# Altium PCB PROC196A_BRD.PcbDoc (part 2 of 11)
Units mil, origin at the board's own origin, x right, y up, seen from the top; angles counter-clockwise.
Board outline 3346.45 x 4921.26 mil, 8 copper layers (Top Layer, GND1, SIG1, PWR1, PWR2, SIG2, GND2, Bottom Layer), stack 54.534 mil thick; 736 components, 498 nets, 3030 pads, 1279 vias.
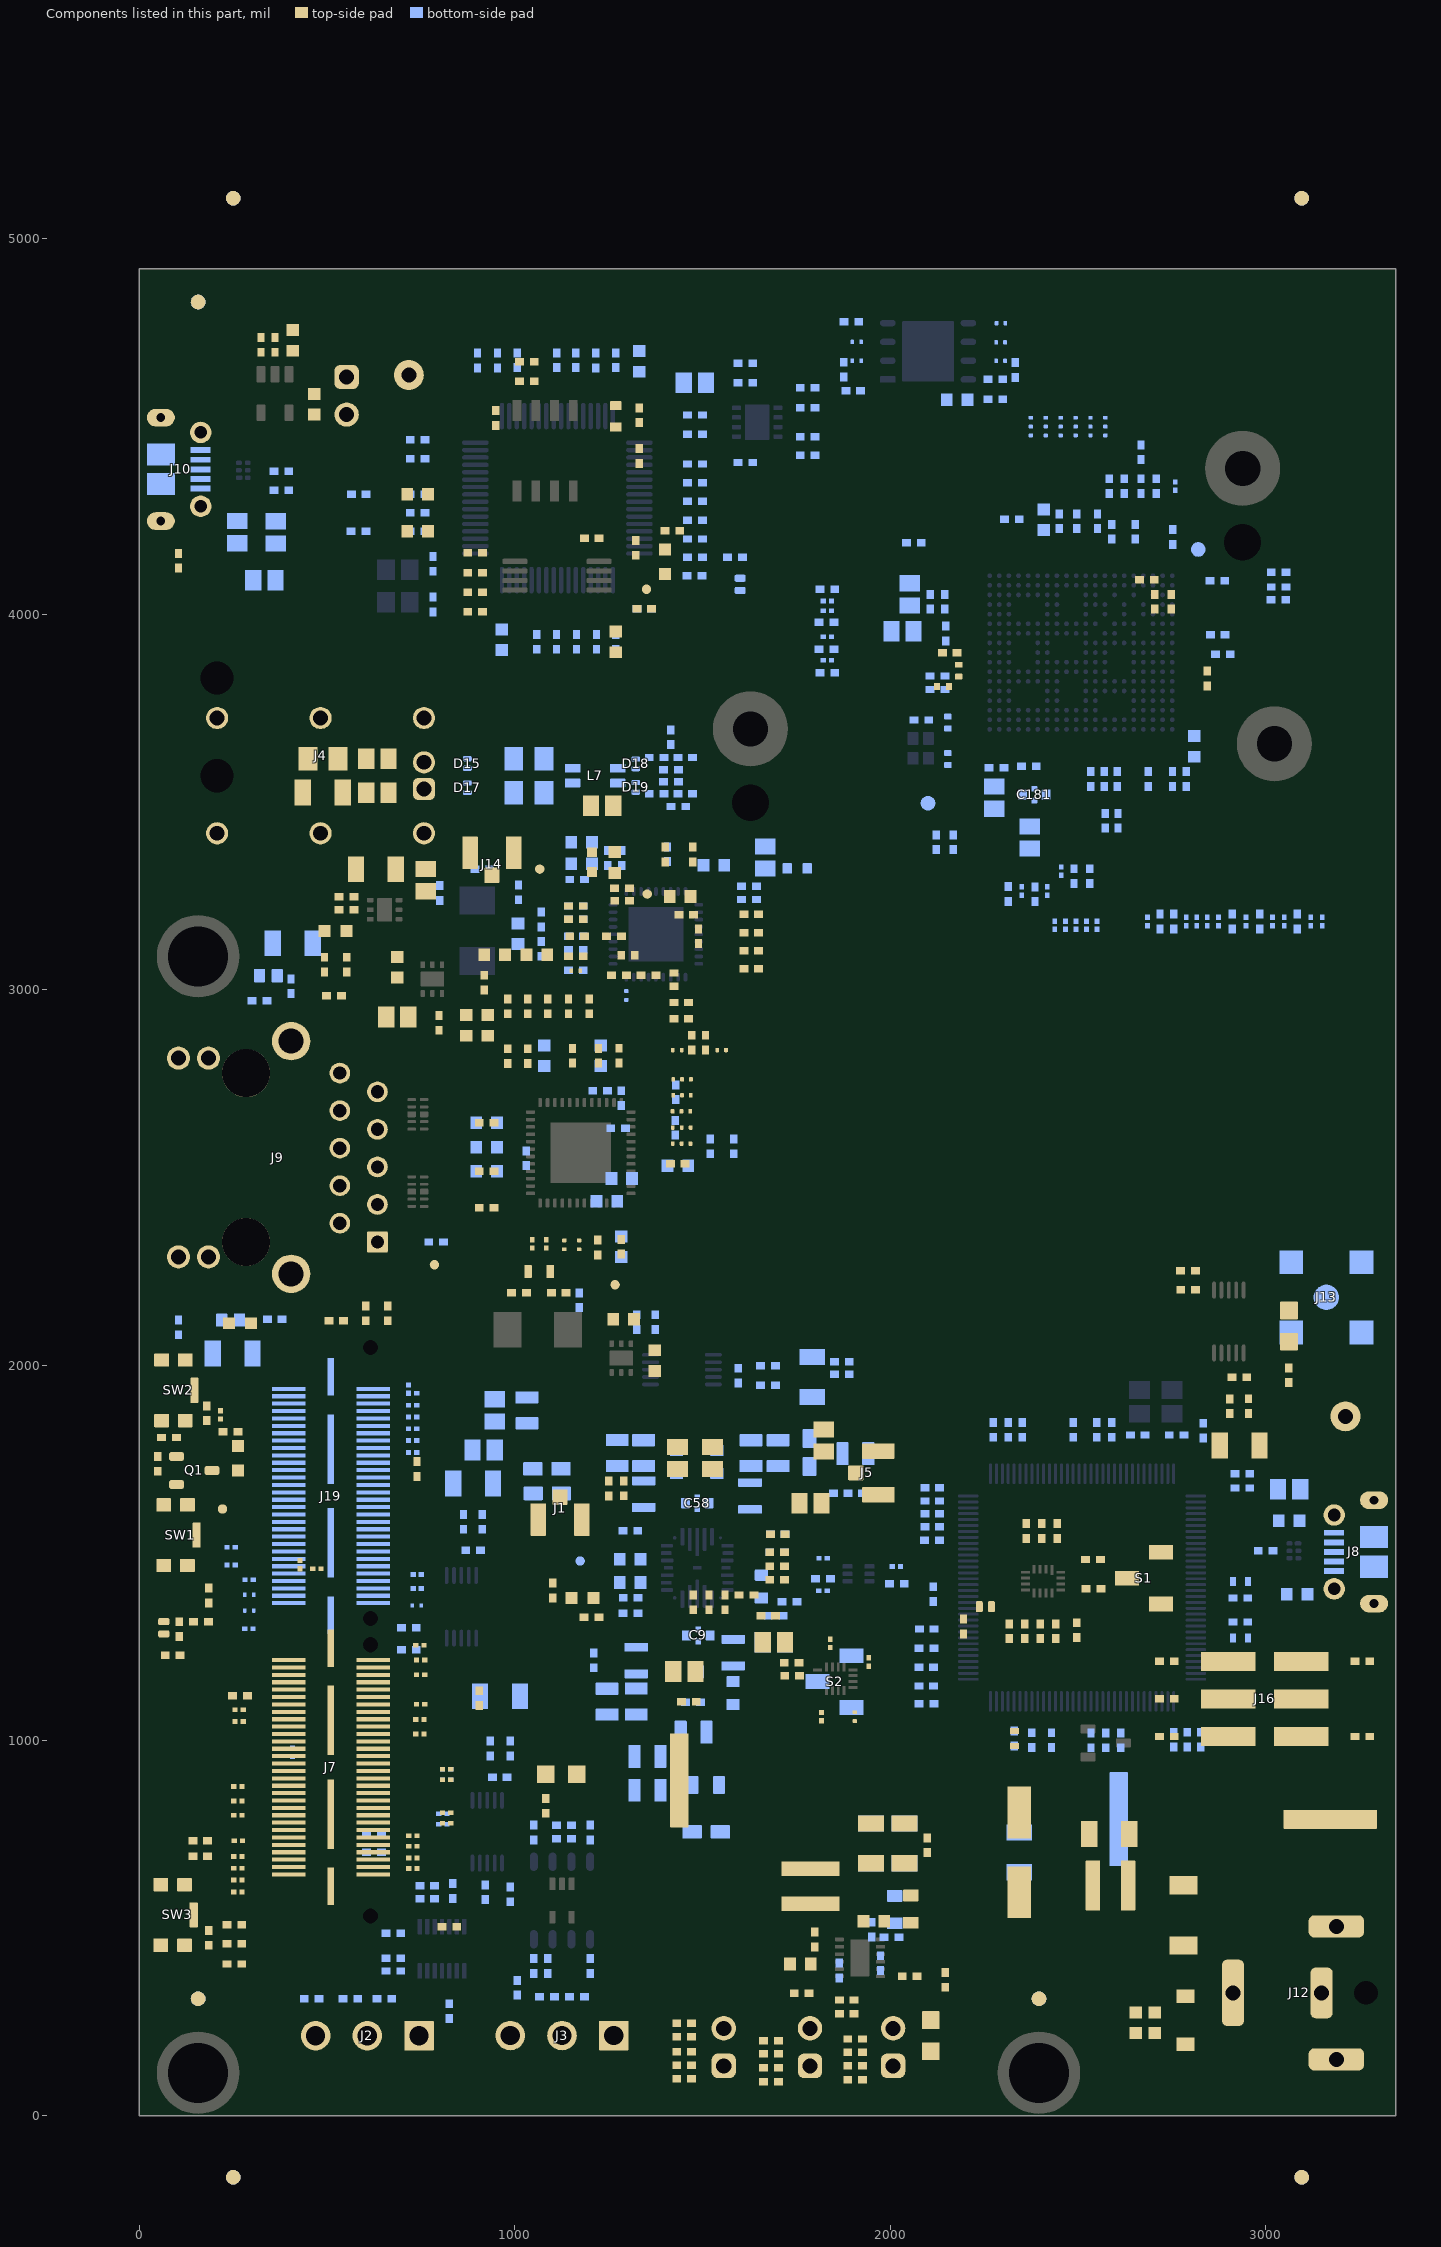
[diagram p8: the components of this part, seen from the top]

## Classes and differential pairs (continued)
differential pair TX2_CLK: +TX2_CLK_P -TX2_CLK_N
differential pair TX1: +TX1_P -TX1_N
differential pair TX0: +TX0_P -TX0_N
differential pair TRD3: +TRD3_P -TRD3_N
differential pair TRD2: +TRD2_P -TRD2_N
differential pair TRD1: +TRD1_P -TRD1_N
differential pair ETH_TRD: +ETH_TRD_P -ETH_TRD_N
differential pair CSI2_CLK: +CSI2_CLK_P -CSI2_CLK_N
differential pair CSI2_1: +CSI2_1_P -CSI2_1_N
differential pair CSI2_0: +CSI2_0_P -CSI2_0_N
differential pair LVDS_TX3_FRCLK: +LVDS_TX3_FRCLK_P -LVDS_TX3_FRCLK_N
differential pair LVDS_TX2_CLK: +LVDS_TX2_CLK_P -LVDS_TX2_CLK_N
differential pair LVDS_TX1: +LVDS_TX1_P -LVDS_TX1_N
differential pair LVDS_TX0: +LVDS_TX0_P -LVDS_TX0_N
differential pair CAN_A: +CANA_P -CANA_N
differential pair CAN_B: +CANB_P -CANB_N
differential pair FTDI_USBD: +FTDI_USBD_P -FTDI_USBD_N
differential pair XDSET_1_D: +XDSET_1_D_P -XDSET_1_D_N
differential pair ETH_TD_4: +TD_4_P -TD_4_N
differential pair ETH_TD_3: +TD_3_P -TD_3_N
differential pair ETH_TD_2: +TD_2_P -TD_2_N
differential pair ETH_TD_1: +TD_1_P -TD_1_N
differential pair CSI2_RX0_CLK: +CSI2_RX0_CLK_P -CSI2_RX0_CLK_N
differential pair CSI2_RX0_1: +CSI2_RX0_1_P -CSI2_RX0_1_N
differential pair CSI2_RX0_0: +CSI2_RX0_0_P -CSI2_RX0_0_N

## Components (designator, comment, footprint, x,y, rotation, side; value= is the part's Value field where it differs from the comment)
C1 "GCM188R71C105KA64D" 0603L 2178.63,4571.73 r0 bottom value=1uF
C2 "CGA2B3X7R1H104K050BB" 0402L 2280.38,4572.73 r180 bottom value=0.1uF
C3 "GCM188R70J225KE22D" 0603L 1307.54,1483.26 r0 bottom value=2.2uF
C4 "C0805C106J8RACAUTO" 0805L 946.64,1879.52 r90 bottom value=10uF
C5 "GCM155R71C224KE02D" 0402L 2107,4033.64 r270 bottom value=0.22uF
C6 "GCJ188C70J475KE02J" FP-GCJ188C70J475KE02J_0603-MFG 1458.73,1183.19 r180 bottom value=4.7µF
C7 "GCM21BR71A106KE22L" 0805L 1526.87,1752.55 r90 top value=10uF
C8 "GCJ188C70J475KE02J" FP-GCJ188C70J475KE02J_0603-MFG 1581.73,1125.98 r90 bottom value=4.7µF
C9 "NFM18HC105C1C3D" FP-NFM18HC105C1C3D_0603-MFG 1489.02,1279.6 r180 bottom
C10 "GCM188R71C105KA64D" 0603L 1761.22,404.47 r180 top value=1uF
C11 "GCM155R71C104KA55D" 0402L 766.94,578.34 r0 bottom value=0.1uF
C12 "GCM155R71C104KA55D" 0402L 834.66,598.77 r270 bottom value=0.1uF
C13 "GCM155R71H472KA37D" 0402L 458.81,311.94 r0 bottom value=4700pF
C14 "GCM155R71A104KA55D" 0402L 960.06,901.73 r0 bottom value=0.1uF
C15 "GCM21BR71A106KE22L" 0805L 1433.57,1752.55 r90 top value=10uF
C16 "GCM155R71C104KA55D" 0402L 1131.24,738.16 r0 bottom value=0.1uF
C17 "GCM155R71A104KA55D" 0402L 1595.68,1972.04 r270 bottom value=0.1uF
C18 "C0402C104K8RACTU" 0402L 1739.01,1172.28 r0 top value=0.1uF
C19 "GCM155R71A104KA55D" 0402L 2930.36,1967.92 r0 top value=0.1uF
C20 "GCM155R71C104KA55D" 0402L 1200.93,398.98 r90 bottom value=0.1uF
C21 "GCM155R71C224KE02D" 0402L 1799.66,469.84 r90 top value=0.22uF
C22 "GCM155R71C224KE02D" 0402L 2099.39,720.8 r90 top value=0.22uF
C23 "GCM31CR71A226KE02L" 1206_180L 2038.6,725.8 r270 bottom value=22uF
C24 "GCM155R71H472KA37D" 0402L 1006.26,341.2 r270 bottom value=4700pF
C25 "GCM31CR71A226KE02L" 1206_180L 2038.6,725.8 r270 top value=22uF
C26 "GCM31CR71A226KE02L" 1206_180L 1949.49,725.8 r270 bottom value=22uF
C27 "C0603C104K4RACAUTO" FP-C0603C104K4RACAUTO_0603-MFG 243.02,2119.9 r0 bottom
C28 "C0603C104K4RACAUTO" FP-C0603C104K4RACAUTO_0603-MFG 343.71,3037.46 r0 bottom
C29 "GCM31CR71A226KE02L" 1206_180L 1949.49,725.8 r270 top value=22uF
C30 "GCM1555C1H270JA16D" 0402L 1117.32,2192.39 r0 top value=27pF
C31 "GCM21BR71A106KE22L" 0805L 1452.03,1183.68 r0 top value=10uF
C32 "GCM188R70J225KE22D" 0603L 1058.91,3092.81 r0 top value=2.2uF
C33 "GCM1555C1H270JA16D" 0402L 1011.33,2192.39 r180 top value=27pF
C34 "GCM155R71H102KA37D" 0402L 798.3,2911.52 r90 top value=1000pF
C35 "CGA2B3X7R1H103K050BB" 0402L 1356.52,3038.39 r0 top value=0.01uF
C36 "GCM155R71C104KA55D" 0402L 1277.78,3038.39 r0 top value=0.1uF
C37 "GCM21BR71A106KE22L" 0805L 1667.73,3352.16 r90 bottom value=10uF
C38 "CGA4J3X7R1H225K125AB" 0805L 687.02,2927.1 r180 top value=2.2uF
C39 "CL21B106KOQNNNE" 0805L 333.24,4091.18 r180 bottom value=10uF
C40 "GCM188R70J225KE22D" 0603L 1530.41,3331.1 r180 bottom value=2.2uF
C41 "GCM155C71A105KE38D" 0402_070 2330.78,1005.16 r270 top value=1uF
C42 "C0402C104K8RACTU" 0402L 2487.6,1827.41 r270 bottom value=0.1uF
C43 "C0402C104K8RACTU" 0402L 2933.19,1379.55 r180 bottom value=0.1uF
C44 "CGA2B3X7R1H103K050BB" 0402L 1624.26,3240.41 r0 bottom value=0.01uF
C45 "CL21B106KOQNNNE" 0805L 3062.92,1669.54 r0 bottom value=10uF
C46 "GCM155R71C104KA55D" 0402L 1624.26,3275.88 r180 bottom value=0.1uF
C47 "C0402C104K8RACTU" 0402L 949.01,4522.91 r90 top value=0.1uF
C48 "GCM188R71C105KA64D" 0603L 687.02,3059.84 r270 top value=1uF
C49 "C0402C104K8RACTU" 0402L 2314.64,1827.41 r90 bottom value=0.1uF
C50 "C0402C103K4RACTU" 0402L 2114.73,1389.65 r90 bottom value=0.01uF
C51 "GCM188R70J225KE22D" 0603L 1178.11,3336.02 r180 bottom value=2.2uF
C52 "CGA2B3X7R1H103K050BB" 0402L 1284.68,3350.79 r90 bottom value=0.01uF
C53 "GCM188R71C105KA64D" 0603L 1229.15,2824.15 r90 bottom value=1uF
C54 "GCM155R71C104KA55D" 0402L 1248.1,3350.79 r270 bottom value=0.1uF
C55 "GRM155R71E473KA88D" 0402L 1162.88,3222.97 r0 bottom value=0.047uF
C56 "GCM188R71C105KA64D" 0603L 925.03,2580.18 r180 bottom value=1uF
C57 "GCM155R71A104KA55D" 0402L 1030.83,2551.09 r270 bottom value=0.1uF
C58 "NFM18HC105C1C3D" FP-NFM18HC105C1C3D_0603-MFG 1486.12,1632.06 r180 bottom
C59 "GCM188R71C105KA64D" 0603L 925.03,2516.33 r180 bottom value=1uF
C60 "GCM188R71C105KA64D" 0603L 1373.01,2012.02 r90 top value=1uF
C61 "GCM155C71A105KE38D" 0402_070 2933.5,1423.7 r0 bottom value=1uF
C62 "GCM155C71A105KE38D" 0402_070 2933.5,1272.74 r0 bottom value=1uF
C63 "GCM1555C1H8R0DA16D" 0402L 2763.45,1813.63 r180 bottom
C64 "C0402C104K8RACTU" 0402L 2933.19,1315.66 r180 bottom value=0.1uF
C65 "GCM188R71C105KA64D" 0603L 1290.01,2122.43 r180 top value=1uF
C66 "C0402C103K4RACTU" 0402L 2614.2,1000.36 r90 bottom value=0.01uF
C67 "C0402C104K8RACTU" 0402L 2574.86,1000.36 r90 bottom value=0.1uF
C68 "C1608X7S1A475K080AC" 0603L 741.44,4221.1 r180 top value=4.7uF
C69 "C0402C104K8RACTU" 0402L 741.44,4221.1 r0 bottom value=0.1uF
C70 "GCM1555C1H8R0DA16D" 0402L 2659.65,1813.63 r180 bottom
C71 "C0402C104K8RACTU" 0402L 2938.61,1710.31 r180 bottom value=0.1uF
C72 "C1608X7S1A475K080AC" 0603L 741.44,4319.53 r180 top value=4.7uF
C73 "C0402C104K8RACTU" 0402L 741.44,4319.53 r0 bottom value=0.1uF
C74 "C1005X7S1A225K050BC" 0402_065L 2550.86,1827.41 r270 bottom value=2.2uF
C75 "C0402C104K8RACTU" 0402L 2590.64,1827.41 r270 bottom value=0.1uF
C76 "C0402C104K8RACTU" 0402L 2330.38,1005.16 r90 bottom value=0.1uF
C77 "C0402C104K8RACTU" 0402L 1345,4014.41 r0 bottom value=0.1uF
C78 "C0402C104K8RACTU" 0402L 1345,4014.41 r0 top value=0.1uF
C79 "C1608X7S1A475K080AC" 0603L 965.97,3932.47 r270 bottom value=4.7uF
C80 "CGA2B3X7R1H104K050BB" 0402L 825.99,278.87 r270 bottom value=0.1uF
C81 "GCM155R71A104KA55D" 0402L 889.05,1506.69 r0 bottom value=0.1uF
C82 "C0402C104K8RACTU" 0402L 1480.11,4400.69 r0 bottom value=0.1uF
C83 "GCM1555C1H8R0DA16D" 0402L 782.36,4134.49 r90 bottom
C84 "GCM1555C1H8R0DA16D" 0402L 782.36,4026.22 r270 bottom
C85 "C1005X7S1A225K050BC" 0402_065L 1614.4,4404.56 r0 bottom value=2.2uF
C86 "C0402C104K8RACTU" 0402L 1205.14,4202.72 r180 top value=0.1uF
C87 "GCM188R71C105KA64D" 0603L 1332.18,4674.03 r90 bottom value=1uF
C88 "C0402C104K8RACTU" 0402L 1269.17,4677.01 r90 bottom value=0.1uF
C89 "C0402C104K8RACTU" 0402L 1480.11,4250.38 r0 bottom value=0.1uF
C90 "GCM188R71C105KA64D" 0603L 1268.76,3926.57 r270 top value=1uF
C91 "C0402C104K8RACTU" 0402L 1268.76,3926.57 r270 bottom value=0.1uF
C92 "GCM155R71C224KE02D" 0402L 2497.58,4248.14 r270 bottom value=0.22uF
C93 "04025A150FAT2A" 0402L 1614.4,4617.01 r0 bottom value=15pF
C94 "C1005X7S1A225K050BC" 0402_065L 1614.4,4668.86 r0 bottom value=2.2uF
C95 "GCM1555C1H270JA16D" 0402L 1070.29,3108.78 r270 bottom value=27pF
C96 "GCM155R71C224KE02D" 0402L 2653.45,4220.14 r270 bottom value=0.22uF
C97 "C0402C104K8RACTU" 0402L 378.25,4330.82 r0 bottom value=0.1uF
C98 "C0402C104K8RACTU" 0402L 2541.82,1403.8 r180 top value=0.1uF
C99 "EEHZC1V680XP" SM_RADIAL_6.3BMM 2344.16,701.75 r90 top value=68uF
C100 "C3216X7R1H475K160AC" 1206_180L 2584.03,750.92 r180 top value=4.7uF
C101 "C3216X7R1H475K160AC" 1206_180L 2344.16,701.75 r90 bottom value=4.7uF
C102 "GRT155R70J105KE01D" FP-GRT155R70J105KE01D_0402-MFG 2182.53,3849.99 r90 top
C103 "GRT155R70J105KE01D" FP-GRT155R70J105KE01D_0402-MFG 2141,3807.81 r180 top
C104 "CGA3E3X8R1H104K080AB" 0603L 2654.4,248.05 r270 top value=0.1uF
C105 "GCM155R71C104KA55D" 0402L 105.96,1296.64 r90 top value=0.1uF
C106 "GCM1555C1H3R9BA16D" FP-GCM1555C1H3R9BA16D_0402-MFG 2153.98,3711.71 r90 bottom value=3.9pF
C107 "GCM155R71C224KE02D" 0402L 2126.32,3835.75 r0 bottom value=0.22uF
C108 "GCM1555C1H3R9BA16D" FP-GCM1555C1H3R9BA16D_0402-MFG 2153.98,3614.48 r270 bottom value=3.9pF
C109 "C0402C103K4RACTU" 0402L 2791.65,1002.31 r90 bottom value=0.01uF
C110 "GCM21BR71A106KE22L" 0805L 2277.53,3511.81 r270 bottom value=10uF
C111 "GCM155R71C224KE02D" 0402L 2126.32,3799.81 r0 bottom value=0.22uF
C112 "GCM21BR71A106KE22L" 0805L 2052,4053.32 r90 bottom value=10uF
C113 "GCM155R71C224KE02D" 0402L 2145.52,4033.64 r270 bottom value=0.22uF
C114 "GCM21BR71A106KE22L" 0805L 2033,3955 r180 bottom value=10uF
C115 "GCM155R71C224KE02D" 0402L 2148.52,3948.96 r90 bottom value=0.22uF
C116 "GCM21BR71A106KE22L" 0805L 2371.99,3405.53 r270 bottom value=10uF
C117 "GCM155R71C224KE02D" 0402L 2369.69,3595.08 r180 bottom value=0.22uF
C118 "CGA4J1X7R1H475K125AC" FP-CGA4J1X7R1H475K125AC_0805-MFG 2055.31,550.68 r270 top value=4.7µF
C119 "GCM21BR71A106KE22L" 0805L 1690.38,1261.41 r0 bottom value=10uF
C120 "GCM21BR71A106KE22L" 0805L 1690.38,1261.41 r0 top value=10uF
C121 "GCM1555C1H270JA16D" 0402L 1070.29,3187.16 r90 bottom value=27pF
C122 "GCM21BR71A106KE22L" 0805L 1232.99,3489.89 r0 top value=10uF
C123 "GCM188R70J225KE22D" 0603L 1307.54,1420.78 r0 bottom value=2.2uF
C124 "GCJ188C70J475KE02J" FP-GCJ188C70J475KE02J_0603-MFG 1657.09,1409.65 r270 bottom value=4.7µF
C125 "CGA4J1X7T0J226M" 0805_155 1629.38,1765.47 r90 bottom value=22uF
C126 "CGA3E3X8R1H104K080AB" 0603L 2705.05,248.05 r270 top value=0.1uF
C127 "CGA4J1X7T0J226M" 0805_155 1701.58,1765.47 r90 bottom value=22uF
C128 "CGA2B3X7R1H104K050BB" 0402L 252.91,509.12 r0 top value=0.1uF
C129 "CGA4J1X7T0J226M" 0805_155 1323.84,1103.87 r270 bottom value=22uF
C130 "CGA4J1X7T0J226M" 0805_155 1245.97,1103.35 r270 bottom value=22uF
C131 "GCM155R71C104KA55D" 0402L 1832.79,4066.99 r0 bottom value=0.1uF
C132 "CGA4J1X7T0J226M" 0805_155 1343.24,1765.47 r90 bottom value=22uF
C133 "C0402C104K8RACTU" 0402L 1821.32,1431.2 r180 bottom value=0.1uF
C134 "CGA4J1X7T0J226M" 0805_155 1273.18,1765.68 r90 bottom value=22uF
C135 "GCM155R71C104KA55D" 0402L 1832.79,3844.85 r0 bottom value=0.1uF
C136 "GCM155R71C104KA55D" 0402L 1830.67,3906.58 r0 bottom value=0.1uF
C137 "GCM188R70J225KE22D" 0603L 2809.92,3648 r90 bottom value=2.2uF
C138 "GCM155R71C224KE02D" 0402L 2749.31,4033.5 r270 top value=0.22uF
C139 "GCM155R71C224KE02D" 0402L 2450.27,4248.14 r270 bottom value=0.22uF
C140 "GCM155R71C224KE02D" 0402L 2535.04,3561.4 r90 bottom value=0.22uF
C141 "GCM155R71C224KE02D" 0402L 2705.12,4033.5 r270 top value=0.22uF
C142 "GCM155R71C224KE02D" 0402L 2684,4092 r180 top value=0.22uF
C143 "CGA4J1X7T0J226M" 0805_155 1476.56,1022 r0 bottom value=22uF
C144 "GCJ188C70J475KE02J" FP-GCJ188C70J475KE02J_0603-MFG 1538.4,1741.87 r270 bottom value=4.7µF
C145 "GCM188R71C105KA64D" 0603L 408.44,4729.82 r90 top value=1uF
C146 "GCM188R70J225KE22D" 0603L 2408.92,4252.13 r270 bottom value=2.2uF
C147 "GCM188R70J225KE22D" 0603L 1266.14,3338.9 r90 top value=2.2uF
C148 "GCM155R71A104KA55D" 0402L 1285.83,3270.67 r0 top value=0.1uF
C149 "GCM188R70J225KE22D" 0603L 466.12,4559.69 r270 top value=2.2uF
C150 "GCM155R71C104KA55D" 0402L 2324.28,4253 r180 bottom value=0.1uF
C151 "CGA4J1X7T0J226M" 0805_155 1032.32,1879.52 r90 bottom value=22uF
C152 "C0805C106J8RACAUTO" 0805L 917.11,1773.67 r180 bottom value=10uF
C153 "GCJ188C70J475KE02J" FP-GCJ188C70J475KE02J_0603-MFG 1430.78,1741.87 r270 bottom value=4.7µF
C154 "CGA2B3X7R1H103K050BB" 0402L 1286.27,3236.75 r0 top value=0.01uF
C155 "GRM1555C1H470FA01D" 0402L 1415.62,3672.6 r270 bottom value=47pF
C156 "GRM1555C1H220FA01D" 0402L 1454.38,3618.51 r0 bottom value=22pF
C157 "CGA4J2X7R2A104K125AA" 0805_HV 1037.67,3615.54 r0 bottom value=0.1uF
C158 "GCM155R71A104KA55D" 0402L 1434.17,2536.83 r0 top value=0.1uF
C159 "GCM188R71C105KA64D" 0603L 1078.54,2824.03 r90 bottom value=1uF
C160 "GCM155R71A104KA55D" 0402L 1153.91,2824.15 r90 top value=0.1uF
C161 "CGA4J2X7R2A104K125AA" 0805_HV 1037.67,3524.99 r0 bottom value=0.1uF
C162 "GRM1555C1H220FA01D" 0402L 1454.38,3522.02 r180 bottom value=22pF
C163 "GCM155R71C224KE02D" 0402L 2570.08,3561.4 r90 bottom value=0.22uF
C164 "GCM155R71C224KE02D" 0402L 2552.55,4248.14 r270 bottom value=0.22uF
C165 "GCM155R71C224KE02D" 0402L 2753.34,4206 r270 bottom value=0.22uF
C166 "GRM1555C1H470FA01D" 0402L 1435.86,3488.17 r0 bottom value=47pF
C167 "GRM31BR73A472KW01L" 1206L 488.5,3525.09 r180 top value=4700pF
C168 "GCM155R71C224KE02D" 0402L 2283.59,3591.08 r0 bottom value=0.22uF
C169 "CGA4J1X7T0J226M" 0805_155 1907.41,1764 r0 bottom value=22uF
C170 "GCM155R71C224KE02D" 0402L 2873,3945.81 r180 bottom value=0.22uF
C171 "GCM188R70J225KE22D" 0603L 1440.53,3248.3 r180 top value=2.2uF
C172 "GCM155R71C224KE02D" 0402L 2844.55,3829 r270 top value=0.22uF
C173 "CGA4J1X7R1H475K125AC" FP-CGA4J1X7R1H475K125AC_0805-MFG 2012.3,549.25 r270 bottom value=4.7µF
C174 "GCM155R71C224KE02D" 0402L 2590.78,4220.14 r270 bottom value=0.22uF
C175 "GCM155R71C224KE02D" 0402L 2605.12,3561.4 r90 bottom value=0.22uF
C176 "GCM155R71C224KE02D" 0402L 2886.48,3893.25 r180 bottom value=0.22uF
C177 "GCM155R71C224KE02D" 0402L 2871.85,4089 r180 bottom value=0.22uF
C178 "GCM155R71A104KA55D" 0402L 1456.97,3199.21 r180 top value=0.1uF
C180 "CGA2B3X7R1H473K050BB" 0402L 2158.91,3897.25 r180 top value=0.047uF
C181 "NFM18HC105C1C3D" FP-NFM18HC105C1C3D_0603-MFG 2384.16,3519.56 r180 bottom
C182 "CGA2B3X7R1H103K050BB" 0402L 1489.66,3142.55 r270 top value=0.01uF
C183 "GCM188R71C105KA64D" 0603L 1245.36,2436.07 r0 bottom value=1uF
C184 "GCM155R71A104KA55D" 0402L 1220.92,2313.15 r270 top value=0.1uF
C185 "GCM155R71A104KA55D" 0402L 1223.15,2824.15 r90 top value=0.1uF
C186 "GCM188R71C105KA64D" 0603L 1434.58,2531.54 r0 bottom value=1uF
C187 "GCM188R71C105KA64D" 0603L 925.03,2645.15 r180 bottom value=1uF
C188 "GCM155R71A104KA55D" 0402L 925.03,2516.33 r180 top value=0.1uF
C189 "GCM155R71A104KA55D" 0402L 925.03,2645.15 r180 top value=0.1uF
C190 "GCM188R71C105KA64D" 0603L 1284.2,2315.32 r270 bottom value=1uF
C191 "GCM155R71A104KA55D" 0402L 1284.2,2315.32 r270 top value=0.1uF
C192 "GCM188R71C105KA64D" 0603L 1285.02,2497.07 r180 bottom value=1uF
C193 "GCM155R71A104KA55D" 0402L 1275.32,2630.46 r180 bottom value=0.1uF
C194 "C0805C106J8RACAUTO" 0805L 1823.26,1799.07 r90 top value=10uF
C195 "CGA3E3X7R1H224K080AB" 0603L 1956.84,517.83 r180 top value=0.22uF
C196 "GCM21BR71A106KE22L" 0805L 763.1,3291.92 r90 top value=10uF
C197 "CGA5L1X7R1H106K160AE" 1206L 629.98,3320.94 r0 top value=10uF
C198 "C0805C106J8RACAUTO" 0805L 1787.88,1631.56 r180 top value=10uF
C199 "GCM155R71C224KE02D" 0402L 1464.06,1103 r0 top value=0.22uF
C200 "GCM155R71C104KA55D" 0402L 1474.75,1101.8 r0 bottom value=0.1uF
C201 "CGA4J1X7T0J226M" 0805_155 1353.58,867.28 r180 bottom value=22uF
C202 "CGA4J1X7T0J226M" 0805_155 1353.58,957.28 r180 bottom value=22uF
"CAUTION HOT SURFACE1" "CAUTION HOT SURFACE" IEC_HotSurface_Small 1476.53,1588.15 r0 top locked
D1 "TLMY1000-GS08" TLMx1000_Yellow 1269.17,4527.56 r270 top value=Yellow
D2 "SMS3923-040LF" SOD-882 2253.83,1356.5 r0 top value=V
D3 "ATV02W280B-HF" SOD-123 2787.46,254.64 r90 top value=28V
D4 "SMS3923-040LF" SOD-882 64.98,1300.09 r90 top value=V
D5 "SMS3923-040LF" SOD-882 1600.48,4079.94 r270 bottom value=V
D6 "SML-LXT0805GW-TR" SML_Green_0805 3062.49,2103.82 r90 top value=Green
D7 "LS L29K-G1J2-1-Z" "LS L29K_Red" 522.64,3156.33 r180 top value=Red
D8 "LS L29K-G1J2-1-Z" "LS L29K_Red" 268.01,2111.42 r180 top value=Red
D9 "SML-E12Y8WT86" SML-E1_Yellow 1400.32,4140.29 r90 top value=Yellow
D10 "SML-P12YTT86" LED_SMLP12_YELLOW 1424,3026.81 r90 top value=Yellow
D11 "FSV530AF" SMAF 2781.96,534.03 r270 top value=30V
D12 "SML-LXT0805GW-TR" SML_Green_0805 2108.41,213.6 r270 top value=Green
D13 "SML-E12Y8WT86" SML-E1_Yellow 262.47,1751.71 r90 top value=Yellow
D14 "SML-P12DTT86" LED_SMLP12_ORANGE 1301.91,3091.95 r0 top value=Orange
D15 "TPD1E05U06QDPYRQ1" DPY0002A 873.77,3602.58 r90 bottom
D16 "SML-LXT0805GW-TR" SML_Green_0805 1124.1,910.02 r0 top value=Green
D17 "TPD1E05U06QDPYRQ1" DPY0002A 873.77,3537.94 r270 bottom
D18 "TPD1E05U06QDPYRQ1" DPY0002A 1322.29,3601.54 r90 bottom
D19 "TPD1E05U06QDPYRQ1" DPY0002A 1322.29,3538.98 r270 bottom
Designator9 "Comment" VGROVE_1-6_45A 9544.57,4519.72 r0 top
DS2 "LS L29K-G1J2-1-Z" "LS L29K_Red" 1180.58,1379.84 r0 top value=Red
"ESD Susceptible1" "ESD Susceptible" ESD_Overlay_Small 1175.93,1141.93 r0 top
FB1 "BLM18HE102SN1D" FP-BLM18AG102SH1D_0603-MFG 1752.76,3323.23 r180 bottom value="1000 ohm"
FB2 "BLM18KG601SH1" "FP-BLM18KG601SH1_0603 (1608 Metric)-MFG" 1206.02,3340.14 r270 top
FID1 "Fiducial" Fiducial10-20 2101,3496.81 r90 bottom
FID2 "Fiducial" Fiducial10-20 2820.77,4173 r90 bottom
FID3 "Fiducial" Fiducial10-20 156.55,311.77 r90 top
FID4 "Fiducial" Fiducial10-20 156.55,311.77 r90 bottom
FID5 "Fiducial" Fiducial10-20 2396.55,311.77 r90 bottom
FID6 "Fiducial" Fiducial10-20 2396.55,311.77 r90 top
FID7 "Fiducial" Fiducial10-20 250,5108.66 r90 bottom
FID8 "Fiducial" Fiducial10-20 250,5108.66 r90 top
FID9 "Fiducial" Fiducial10-20 156.55,4831.99 r90 bottom
FID10 "Fiducial" Fiducial10-20 156.55,4831.99 r90 top
FID11 "Fiducial" Fiducial10-20 3096.45,5108.66 r90 bottom
FID12 "Fiducial" Fiducial10-20 250,-163.78 r90 top
FID13 "Fiducial" Fiducial10-20 250,-163.78 r90 bottom
FID14 "Fiducial" Fiducial10-20 3096.45,5108.66 r90 top
FID15 "Fiducial" Fiducial10-20 3096.45,-163.78 r90 bottom
FID16 "Fiducial" Fiducial10-20 3096.45,-163.78 r90 top
J1 "1909763-1" "FP-1909763-1_SMT_JACK _CONN-MFG" 1120.81,1585.4 r180 top
J2 "OSTTF030161" FP-OSTTF030161_PTH_TERMINAL_BLOCK-MFG 607.34,195.71 r180 top locked
J3 "OSTTF030161" FP-OSTTF030161_PTH_TERMINAL_BLOCK-MFG 1125.93,196.1 r180 top locked
J4 "9-2304372-9" TE_9-2304372-9 207.07,3570.26 r90 bottom
J5 "1909763-1" "FP-1909763-1_SMT_JACK _CONN-MFG" 1971.89,1712.86 r270 top
J7 "QSH-030-01-L-D-A" Samtec_QSH-030-01-X-D-A 510.29,928.61 r0 top locked
J8 "105017-0001" CONN_105017-0001 3236.21,1502.23 r270 bottom
J9 "LPJG16414A4NL" FP-LPJG16414A4NL_CONN_RJ45-MFG 279.25,2552.93 r90 bottom
J10 "105017-0001" CONN_105017-0001 110.24,4386.21 r90 bottom
J12 "PJ-063AH" CUI_PJ-063AH 3090.58,327.49 r0 bottom
J13 "142-0711-201" 142-0711-201 3162.24,2180.42 r180 bottom
J14 "128-0711-201" Johnson_128-0711-201 939.4,3364.85 r180 top
J16 "TSM-103-01-L-DV" Samtec_TSM-103-01-x-DV 2997.83,1110.62 r0 top
J17 "TSW-102-07-G-S" TSW-102-07-G-S 1556.83,183.08 r90 top
J18 "TSW-102-07-G-S" TSW-102-07-G-S 1786.64,183.08 r90 top
J19 "Receptacle_30x2_4MP_LeftRight" Samtec_QSH-030-01-X-D-A 510.29,1651.13 r0 bottom locked
J20 "TSW-102-07-G-S" TSW-102-07-G-S 2007.9,183.08 r90 top
J21 "GBC01SFBN-M30" Sullins_GBC01SFBN-M30 2608.9,690.39 r180 bottom
J22 "GBC01SFBN-M30" Sullins_GBC01SFBN-M30 1438.23,793.66 r0 top
J23 "GBC01SFBN-M30" Sullins_GBC01SFBN-M30 3272.58,789.57 r90 top
L1 "TFM201610ALMA1R5MTAA" TFM201610ALMA 1581.92,1233.84 r270 bottom value=1.5uH
L2 "TFM201610ALMAR24MTAA" "FP-TFM201610ALMAR24MTAA_0806 (2016 Metric)-MFG" 1323.63,1212.76 r270 bottom value=0.24uH
L3 "BLM15HG601SN1D" 0402L 583.79,4221.1 r0 bottom value="600 ohm"
L4 "BLM15HG601SN1D" 0402L 584.54,4319.53 r0 bottom value="600 ohm"
L5 "XAL4030-472MEC" FP-XAL4030-472MEC_SMD2-MFG 2587.17,613.75 r180 top value=4.7µH
L6 "XEL4030-222MEB" XEL4030_310 1787.95,611.97 r90 top value=2.2uH
L7 "ACT1210L-201-2P-TL00" FP-ACT1210L-201-2P-TL00_SMD4-MFG 1214.23,3570.26 r180 bottom
L8 "TFM201610ALMAR24MTAA" "FP-TFM201610ALMAR24MTAA_0806 (2016 Metric)-MFG" 1343.51,1656.08 r90 bottom value=0.24uH
L9 "TFM201610ALMAR24MTAA" "FP-TFM201610ALMAR24MTAA_0806 (2016 Metric)-MFG" 1626.8,1651.25 r90 bottom value=0.24uH
L10 "MPZ2012S101ATD25" FP-MPZ2012S101ATD25_0805-MFG 1509.05,881.24 r180 bottom
LBL1 "THT-14-423-10" Label_650x200 3128.17,899.25 r90 bottom value=xWR2944EVM
Logo1 "Texas Instruments" TI_Stacked_Overlay_Small 2303.59,2109.81 r0 top
LOGO2 "CE Mark" CE_Mark_5mm 520.8,1619.37 r0 top
Logo3 "FCC disclaimer" FCC_disclaimer 4097.26,11224.1 r90 top
Logo4 "WEEE logo" WEEE_Minimum 1688.39,938.45 r0 top
Logo5 "UKCA Marking" -UKCA_Filled 540.33,1892.81 r0 top
NT1 "Net-Tie" Net-Tie_50milWide_30milLong 1556.4,1461.72 r180 top net-tie
NT2 "Net-Tie" Net-Tie_50milWide_30milLong 1485.93,1506.39 r90 top net-tie
NT3 "Net-Tie" Net-Tie_50milWide_30milLong 1485.18,1410 r270 top net-tie
NT4 "Net-Tie" Net-Tie_50milWide_30milLong 1416.27,1458.5 r180 top net-tie
P1 "TSW-102-07-G-S" TSW-102-07-G-S 552.17,4582.33 r270 top
Q1 "BSS123" SOT-23 146.25,1719.23 r0 top value=100V
R1 "ERJ-2GE0R00X" 0402L 1764.22,326.87 r180 top value=0
R2 "CRCW04027K50FKED" 0402L 1864.88,387.17 r90 bottom value=7.50k
R3 "ERJ-2GE0R00X" 0402L 3034.44,4038.75 r180 bottom value=0
R4 "ERJ-2GE0R00X" 0402L 2051.97,371.42 r180 top value=0
R5 "ERJ-2GE0R00X" 0402L 2737.45,1210.62 r0 top value=0
R6 "ERJ-2GE0R00X" 0402L 1974.33,406.85 r270 bottom value=0
R7 "CRCW040210K0FKED" 0402L 2003.88,476.14 r180 bottom value=10.0k
R8 "CRCW040210K0FKED" 0402L 1950.73,495.83 r90 bottom value=10.0k
R9 "CRCW040210K0FKED" 0402L 1884.57,271.68 r0 top value=10.0k
R10 "CRCW040210K0FKED" 0402L 1884.57,308.55 r180 top value=10.0k
R11 "ERJ-2GE0R00X" 0402L 1050.93,754.72 r270 bottom value=0
R12 "ERJ-2GE0R00X" 0402L 1200.93,754.72 r270 bottom value=0
R13 "ERJ-2GE0R00X" 0402L 1517.62,1367.79 r90 top value=0
R14 "ERJ-2GE0R00X" 0402L 1868.6,1658.96 r180 bottom value=0
R15 "CRCW040261R9FKED" 0402L 562.07,311.94 r0 bottom value=61.9
R16 "ERJ-2GE0R00X" 0402L 766.94,612.55 r180 bottom value=0
R17 "ERJ-2GE0R00X" 0402L 1560.12,1367.79 r90 top value=0
R18 "CRCW040210K0FKED" 0402L 676.83,419.53 r0 bottom value=10.0k
R19 "CRCW040210K0FKED" 0402L 676.83,385.8 r180 bottom value=10.0k
R20 "ERJ-2GE0R00X" 0402L 1250.68,1671.33 r90 top value=0
R21 "ERJ-2GE0R00X" 0402L 676.83,486.19 r0 bottom value=0
R22 "ERJ-2GE0R00X" 0402L 3085,3181.79 r90 bottom value=0
R23 "ERJ-2GE0R00X" 0402L 2984.98,3181.79 r90 bottom value=0
R24 "CRCW040261R9FKED" 0402L 652.61,311.94 r0 bottom value=61.9
R25 "ERJ-2GE0R00X" 0402L 825.99,503.91 r180 top value=0
R26 "CRCW040210R2FKED" 0402L 934.47,978.39 r270 bottom value=10.2
R27 "ERJ-2GE0R00X" 0402L 625.03,702.3 r180 bottom value=0
R28 "RMCF0603ZT0R00" 0603L 946.55,3092.81 r0 top value=0
R29 "ERJ-2GE0R00X" 0402L 625.03,752.49 r180 bottom value=0
R30 "CSNL1206FT1L00" 1206L 960.56,1117.62 r180 bottom value=0.001
R31 "ERJ-2GE0R00X" 0402L 3035.16,4111.81 r180 bottom value=0
R32 "CRCW040210R2FKED" 0402L 987.91,978.39 r270 bottom value=10.2
R33 "ERJ-2GE0R00X" 0402L 1325.38,2114.32 r90 bottom value=0
R34 "CRCW04022K20JNED" 0402L 1162.88,3052.21 r0 bottom value=2.2k
R35 "ERJ-2GE0R00X" 0402L 1374.75,2114.32 r90 bottom value=0
R36 "CRCW040210R2FKED" 0402L 2195.53,1303.68 r90 top value=10.2
R37 "ERJ-2GE0R00X" 0402L 2280.38,4626.23 r180 bottom value=0
R38 "CRCW040247K5FKED" 0402L 1901.95,4595.86 r180 bottom value=47.5k
R39 "ERJ-1GNF33R2C" FP-ERJ-1GNF33R2C_0201-MFG 1910.95,4675.55 r0 bottom value=33.2
R40 "ERJ-1GNF33R2C" FP-ERJ-1GNF33R2C_0201-MFG 2294.45,4675.21 r0 bottom value=33.2
R41 "CRCW040210K0FKED" 0402L 2333.26,4650.9 r270 bottom value=10.0k
R42 "ERJ-1GNF33R2C" FP-ERJ-1GNF33R2C_0201-MFG 1910.95,4725.85 r0 bottom value=33.2
R43 "CRCW040210K0FKED" 0402L 1896.94,4779.29 r0 bottom value=10.0k
R44 "ERJ-1GNF33R2C" FP-ERJ-1GNF33R2C_0201-MFG 2294.45,4724.57 r0 bottom value=33.2
R45 "ERJ-1GNF33R2C" FP-ERJ-1GNF33R2C_0201-MFG 2295.32,4775.85 r0 bottom value=33.2
R46 "CRCW040210K0FKED" 0402L 1162.88,3088.99 r0 top value=10.0k
R47 "CRCW040210R2FKED" 0402L 1674.81,1998.09 r180 bottom value=10.2
R48 "BLM18KG601SH1" 0603L 1178.11,3393.27 r0 bottom
R49 "CRCW040210K0FKED" 0402L 1876.26,4651.97 r270 bottom value=10.0k
R50 "ERJ-2GE0R00X" 0402L 1162.88,3187.4 r180 top value=0
R51 "ERJ-2GE0R00X" 0402L 1162.88,3187.4 r180 bottom value=0
R52 "CRCW04023K30JNED" 0402L 252.91,458.31 r0 top value=3.3k
R53 "CRCW04024K70JNED" 0402L 987.76,589.89 r270 bottom value=4.7k
R54 "ERJ-2GE0R00X" 0402L 921.27,595.53 r270 bottom value=0
R55 "CRCW040233K0JNED" 0402L 252.91,404.47 r180 top value=33k
R56 "CRCW040210R2FKED" 0402L 863.5,1582.24 r270 bottom value=10.2
R57 "ERJ-2GE0R00X" 0402L 717.8,1300.21 r180 bottom value=0
R58 "ERJ-2GE0R00X" 0402L 2794.16,2200.17 r180 top value=0
R59 "ERJ-2GE0R00X" 0402L 2793.79,2251 r180 top value=0
R60 "CSNL1206FT1L00" 1206L 1792.45,1968.16 r90 bottom value=0.001
R61 "ERJ-2GE0R00X" 0402L 3258.21,1210.62 r0 top value=0
R62 "ERJ-2GE0R00X" 0402L 717.8,1241.15 r180 bottom value=0
R63 "ERJ-2GE0R00X" 0402L 1700.6,1549.25 r0 bottom value=0
R64 "CSNL1206FT1L00" 1206L 889.22,1684.62 r180 bottom value=0.001
R65 "CRCW040210R2FKED" 0402L 1674.81,1946.4 r180 bottom value=10.2
R66 "CRCW040210R2FKED" 0402L 913.54,1582.24 r270 bottom value=10.2
R67 "ERJ-2GE0R00X" 0402L 1946.52,1658.96 r0 bottom value=0
R68 "CRCW0402220RJNED" 0402L 104.25,2100.54 r90 bottom value=220
R69 "CRCW0402220RJNED" 0402L 320.09,2970.41 r0 bottom value=220
R70 "ERJ-2GE0R00X" 0402L 1204.36,1327.81 r180 top value=0
R71 "ERJ-2GE0R00X" 0402L 1290.05,1671.46 r90 top value=0
R72 "CRCW02010000Z0ED" 0201L 427.98,1468.54 r90 top value=0
R73 "HCJ0603ZT0R00" FP-HCJ0603ZT0R00_0603-MFG 1085.67,1723.53 r180 bottom value=0
R74 "ERJ-1GNF33R2C" FP-ERJ-1GNF33R2C_0201-MFG 2375.03,4512.12 r90 bottom value=33.2
R75 "ERJ-2GE0R00X" 0402L 1308.08,1558.22 r0 bottom value=0
R76 "ERJ-2GE0R00X" 0402L 1308.93,1379.84 r0 bottom value=0
R77 "ERJ-2RKF4700X" 0402L 1443.57,2965.88 r180 top value=470
R78 "ERJ-2GE0R00X" 0402L 1131.24,774.22 r180 bottom value=0
R79 "CRCW04022K49FKED" 0402L 1443.57,2922.81 r180 top value=2.49k
R80 "CRCW02010000Z0ED" 0201L 1832.79,3940.53 r180 bottom value=0
R81 "CRCW02010000Z0ED" 0201L 749.22,1214.04 r180 top value=0
R82 "CRCW02010000Z0ED" 0201L 1832.79,3877.49 r180 bottom value=0
R83 "CRCW02010000Z0ED" 0201L 1832.79,4035.43 r180 bottom value=0
R84 "CRCW02010000Z0ED" 0201L 747.25,1253.41 r180 top value=0
R85 "CRCW040261R9FKED" 0402L 1085.8,317.57 r0 bottom value=61.9
R86 "CRCW040210K0FKED" 0402L 1050.93,398.98 r270 bottom value=10.0k
R87 "CRCW040261R9FKED" 0402L 1166.06,317.57 r0 bottom value=61.9
R88 "ERJ-2GE0R00X" 0402L 2123.18,3392.81 r90 bottom value=0
R89 "CRCW04022K49FKED" 0402L 1166.09,3142.2 r180 top value=2.49k
R90 "ERJ-2GE0R00X" 0402L 913.4,3320.81 r0 bottom value=0
R91 "CRCW02010000Z0ED" 0201L 408.15,968.36 r270 bottom value=0
R92 "CRCW04022K49FKED" 0402L 981.5,2955.6 r90 top value=2.49k
R93 "ERJ-2RKF4700X" 0402L 1264.51,3142.2 r180 top value=470
R94 "CRCW02010000Z0ED" 0201L 1832.79,4009.45 r180 bottom value=0
R95 "ERJ-2GE0R00X" 0402L 2167.78,3392.81 r90 bottom value=0
R96 "ERJ-1GNF33R2C" FP-ERJ-1GNF33R2C_0201-MFG 2414.73,4512.12 r90 bottom value=33.2
R97 "CRCW04022K49FKED" 0402L 981.5,2822.91 r90 top value=2.49k
R98 "ERJ-1GNF33R2C" FP-ERJ-1GNF33R2C_0201-MFG 2375.03,4488.5 r270 bottom value=33.2
R99 "CRCW04021K00FKED" 0402L 1699.06,1428.39 r180 top value=1.00k
R100 "ERJ-1GNF33R2C" FP-ERJ-1GNF33R2C_0201-MFG 2494.11,4512.12 r90 bottom value=33.2
R101 "ERJ-1GNF33R2C" FP-ERJ-1GNF33R2C_0201-MFG 2454.42,4488.5 r270 bottom value=33.2
R102 "CRCW040210K0FKED" 0402L 1699.06,1464.28 r0 top value=10.0k
R103 "ERJ-1GNF33R2C" FP-ERJ-1GNF33R2C_0201-MFG 2414.73,4488.5 r270 bottom value=33.2
R104 "HCJ0603ZT0R00" FP-HCJ0603ZT0R00_0603-MFG 1785.37,1767.32 r90 bottom value=0
R105 "ERJ-1GNF33R2C" FP-ERJ-1GNF33R2C_0201-MFG 2494.11,4488.5 r270 bottom value=33.2
R106 "CRCW040210K0FKED" 0402L 1617.48,1387.47 r0 top value=10.0k
R107 "ERJ-2GE0R00X" 0402L 2709,4341.41 r270 bottom value=0
R108 "ERJ-2RKF4700X" 0402L 552.17,3066.83 r270 top value=470
R109 "ERJ-2GE0R00X" 0402L 2668.4,4341.41 r270 bottom value=0
R110 "CRCW040210R0JNED" 0402L 184.83,474.05 r270 top value=10
R111 "HCJ0603ZT0R00" FP-HCJ0603ZT0R00_0603-MFG 1086.83,1657.99 r180 bottom value=0
R112 "CRCW04022K49FKED" 0402L 518.7,2983.59 r0 top value=2.49k
R113 "ERJ-2GE0R00X" 0402L 493.11,3066.83 r90 top value=0
R114 "CRCW02010000Z0ED" 0201L 262.34,596.46 r0 top value=0
R115 "CRCW02010000Z0ED" 0201L 749.22,1096.36 r180 top value=0
R116 "CRCW04020000Z0EDHP" 0402L 1694.99,1332.02 r0 bottom value=0
R117 "ERJ-2GE0R00X" 0402L 603.35,2137.94 r90 top value=0
R118 "CRCW04022K49FKED" 0402L 661.43,2137.94 r90 top value=2.49k
R119 "CRCW12061M00JNEA" 1206L 408.52,3123.81 r180 bottom value=1.0Meg
R120 "ERJ-2RKF4700X" 0402L 524.61,2118.25 r180 top value=470
R121 "ERJ-1GNF33R2C" FP-ERJ-1GNF33R2C_0201-MFG 2573.5,4512.12 r90 bottom value=33.2
R122 "ERJ-1GNF33R2C" FP-ERJ-1GNF33R2C_0201-MFG 2533.81,4488.5 r270 bottom value=33.2
R123 "CRCW04021K00FKED" 0402L 2112.27,1673.35 r180 bottom value=1.00k
R124 "CRCW04021K00FKED" 0402L 2112.27,1604.01 r180 bottom value=1.00k
R125 "CRCW040210K0FKED" 0402L 1308.37,1339.21 r180 bottom value=10.0k
R126 "CRCW04021K00FKED" 0402L 2112.27,1637.75 r180 bottom value=1.00k
R127 "CRCW04021K00FKED" 0402L 2112.27,1569.43 r180 bottom value=1.00k
R128 "ERJ-2GE0R00X" 0402L 2096.97,1097.79 r0 bottom value=0
R129 "ERJ-2GE0R00X" 0402L 2096.4,1145.19 r0 bottom value=0
R130 "CRCW12061M00JNEA" 1206L 248.33,2030.64 r180 bottom value=1.0Meg
R131 "ERJ-2GE0R00X" 0402L 2430.04,1000.94 r90 bottom value=0
R132 "CRCW04022K49FKED" 0402L 1034.65,2955.6 r90 top value=2.49k
R133 "CRCW04021K00FKED" 0402L 739.54,1722.98 r270 top value=1.00k
R134 "CRCW040249R9FKED" 0402L 2275.06,1827.41 r90 bottom value=49.9
R135 "CRCW02010000Z0ED" 0201L 727.89,1767.32 r180 bottom value=0
R136 "ERJ-2GE0R00X" 0402L 2377.63,1000.94 r90 bottom value=0
R137 "CRCW04022K49FKED" 0402L 1034.65,2822.91 r90 top value=2.49k
R138 "CRCW02010000Z0ED" 0201L 727.89,1798.82 r180 bottom value=0
R139 "CRCW04022K49FKED" 0402L 1227.43,2730.45 r180 bottom value=2.49k
R140 "CRCW04021K00FKED" 0402L 2535.11,1000.36 r270 bottom value=1.00k
R141 "CRCW04022K49FKED" 0402L 1198.68,2955.53 r90 top value=2.49k
R142 "CRCW04022K49FKED" 0402L 1277.72,2824.25 r90 top value=2.49k
R143 "CRCW04022K49FKED" 0402L 1284.09,2711.25 r90 bottom value=2.49k
R144 "CRCW040233R2FKED" 0402L 741.44,4465.4 r180 bottom value=33.2
R145 "CRCW040233R2FKED" 0402L 900.95,4676.27 r90 bottom value=33.2
R146 "ERJ-2GE0R00X" 0402L 954.15,4676.24 r90 bottom value=0
R147 "CRCW040233R2FKED" 0402L 1006.27,4676.97 r90 bottom value=33.2
R148 "ERJ-2GE0R00X" 0402L 1111.81,4677.01 r90 bottom value=0
R149 "ERJ-2GE0R00X" 0402L 1162.88,4677.01 r90 bottom value=0
R150 "ERJ-2GE0R00X" 0402L 1215.81,4676.29 r90 bottom value=0
R151 "ERJ-2GE0R00X" 0402L 1480.11,4531.01 r0 bottom value=0
R152 "ERJ-2GE0R00X" 0402L 2833.89,1825.45 r270 bottom value=0
R153 "ERJ-2GE0R00X" 0402L 1480.11,4479.83 r0 bottom value=0
R154 "ERJ-2GEJ101X" 0402L 2938.61,1672.6 r0 bottom value=100
R155 "CRCW040210K0FKED" 0402L 2352.4,1827.41 r90 bottom value=10.0k
R156 "CRCW04026K04FKED" 0402L 1871.41,2008.78 r180 bottom value=6.04k
R157 "CRCW040210K0FKED" 0402L 741.44,4270.79 r0 bottom value=10.0k
R158 "ERJ-2GE0R00X" 0402L 1478.98,4102.86 r0 bottom value=0
R159 "CRCW04021K00FKED" 0402L 323.96,4718.01 r270 top value=1.00k
R160 "ERJ-2GE0R00X" 0402L 1480.11,4350.15 r0 bottom value=0
R161 "MCT06030Z0000ZP500" 0603L 3062.92,1585.36 r180 bottom value=0
R162 "ERJ-2GE0R00X" 0402L 1217.86,3926.57 r270 bottom value=0
R163 "CRCW04021K00FKED" 0402L 741.44,4415.03 r0 bottom value=1.00k
R164 "ERJ-2GE0R00X" 0402L 1480.11,4301.11 r0 bottom value=0
R165 "CRCW02010000Z0ED" 0201L 2439,3171.79 r270 bottom value=0
R166 "ERJ-2GE0R00X" 0402L 1480.11,4200.6 r0 bottom value=0
R167 "ERJ-2GE0R00X" 0402L 2737.45,1110.62 r0 top value=0
R168 "CRCW02010000Z0ED" 0201L 727.89,1830.31 r180 bottom value=0
R169 "CRCW040233R2FKED" 0402L 1164.49,3926.57 r270 bottom value=33.2
R170 "CRCW040233R2FKED" 0402L 1111.12,3926.57 r270 bottom value=33.2
R171 "CRCW040233R2FKED" 0402L 1058.91,3926.57 r270 bottom value=33.2
R172 "CRCW040210K5FKED" 0402L 1871.41,1975.11 r0 bottom value=10.5k
R173 "CRCW04022K49FKED" 0402L 1427.4,2632.16 r90 bottom value=2.49k
R174 "CRCW040230K0FKED" 0402L 3000.5,1505.18 r0 bottom value=30.0k
R175 "MCT06030Z0000ZP500" 0603L 3084.51,1389.75 r0 bottom value=0
R176 "ERJ-2GE0R00X" 0402L 2737.45,1010.62 r0 top value=0
R177 "CRCW040210K0FKED" 0402L 1088.45,398.98 r90 bottom value=10.0k
R178 "ERJ-1GNF33R2C" FP-ERJ-1GNF33R2C_0201-MFG 2573.5,4488.5 r270 bottom value=33.2
R179 "CRCW040233R2FKED" 0402L 1332.18,4421.89 r90 top value=33.2
R180 "ERJ-2GEJ511X" 0402L 1332.18,4530.43 r270 top value=510
R181 "ERJ-2GE0R00X" 0402L 1322.15,4177.23 r270 top value=0
R182 "CRCW08050000Z0EA" 0805L 1480.13,4617.01 r180 bottom value=0
R183 "CRCW0402100KFKED" 0402L 1780.35,4423.56 r0 bottom value=100k
R184 "CRCW040210K0FKED" 0402L 894.35,4110.53 r180 top value=10.0k
R185 "ERJ-2GE0R00X" 0402L 3258.21,1010.62 r0 top value=0
R186 "ERJ-2GE0R00X" 0402L 1731.91,1369.65 r0 bottom value=0
R187 "CRCW040210K0FKED" 0402L 894.35,4164.3 r180 top value=10.0k
R188 "CRCW02010000Z0ED" 0201L 1943.39,1209.02 r90 top value=0
R189 "CRCW02010000Z0ED" 0201L 727.89,1861.81 r180 bottom value=0
R190 "ERJ-2GE0R00X" 0402L 1699.06,1501.05 r180 top value=0
R191 "CRCW02010000Z0ED" 0201L 727.89,1893.3 r180 bottom value=0
R192 "CRCW02010000Z0ED" 0201L 727.89,1924.8 r180 bottom value=0
R193 "CRCW040233R2FKED" 0402L 1700.6,1549.25 r0 top value=33.2
R194 "CRCW04024K87FKED" 0402L 2111.68,1533.4 r0 bottom value=4.87k
R195 "ERJ-1GNF33R2C" FP-ERJ-1GNF33R2C_0201-MFG 1433.03,2839.29 r180 top value=33.2
R196 "CRCW02010000Z0ED" 0201L 716.86,1935.82 r90 bottom value=0
R197 "CRCW02010000Z0ED" 0201L 262.34,659.45 r0 top value=0
R198 "CRCW02010000Z0ED" 0201L 262.34,627.95 r0 top value=0
R199 "CRCW04020000Z0EDHP" 0402L 1675.3,1332.02 r0 top value=0
R200 "HCJ0603ZT0R00" FP-HCJ0603ZT0R00_0603-MFG 1510.27,756.38 r180 bottom value=0
R201 "CRCW040210K0FKED" 0402L 894.35,4006.75 r0 top value=10.0k
R202 "CRCW040249K9FKED" 0402L 1780.35,4603.23 r0 bottom value=49.9k
R203 "CRCW040229K4FKED" 0402L 1780.35,4550.19 r0 bottom value=29.4k
R204 "CRCW0402100KFKED" 0402L 1780.35,4473.42 r180 bottom value=100k
R205 "CRCW04022K20JNED" 0402L 894.35,4059.35 r0 top value=2.2k
R206 "CRCW08050000Z0EA" 0805L 261.15,4219.15 r270 bottom value=0
R207 "CRCW08050000Z0EA" 0805L 363.17,4218.32 r270 bottom value=0
R208 "CRCW040230K0FKED" 0402L 378.25,4381.16 r180 bottom value=30.0k
R209 "ERJ-2GE0R00X" 0402L 104.25,4142.83 r90 top value=0
R210 "CRCW040210K0FKED" 0402L 1475.62,1367.79 r270 top value=10.0k
R211 "CRCW04025K76FKED" 0402L 1471.91,2858.98 r90 top value=5.76k
R212 "CRCW02010000Z0ED" 0201L 2455.7,3316.02 r270 bottom value=0
R213 "ERJ-2GE0R00X" 0402L 2687.85,3561.4 r270 bottom value=0
R214 "ERJ-2GE0R00X" 0402L 2755.57,3181.79 r270 bottom value=0
R215 "CRCW02010000Z0ED" 0201L 262.36,877.1 r0 top value=0
R216 "CRCW02010000Z0ED" 0201L 2467,3171.79 r270 bottom value=0
R217 "RC0201JR-0710RL" 0201L 2789.3,3181.79 r90 bottom value=10
R218 "CRCW02010000Z0ED" 0201L 2817.15,3181.79 r270 bottom value=0
R219 "CRCW02010000Z0ED" 0201L 2495,3171.79 r270 bottom value=0
R220 "CRCW02010000Z0ED" 0201L 2845,3181.79 r270 bottom value=0
R221 "RC0201JR-0710RL" 0201L 2523,3171.79 r90 bottom value=10
R222 "CRCW040210K0FKED" 0402L 2017.88,1417.16 r0 bottom value=10.0k
R223 "CRCW02010000Z0ED" 0201L 1840.23,1258.68 r90 top value=0
R224 "CRCW02010000Z0ED" 0201L 3120.48,3181.79 r270 bottom value=0
R225 "ERJ-1GNF33R2C" FP-ERJ-1GNF33R2C_0201-MFG 2533.81,4512.12 r90 bottom value=33.2
R226 "CRCW02010000Z0ED" 0201L 472.98,1457.42 r0 top value=0
R227 "RC0201JR-0710RL" 0201L 3151,3181.79 r90 bottom value=10
R228 "RC0201JR-0710RL" 0201L 2875,3181.79 r90 bottom value=10
R229 "CRCW02010000Z0ED" 0201L 3018.9,3181.79 r270 bottom value=0
R230 "ERJ-1GNF33R2C" FP-ERJ-1GNF33R2C_0201-MFG 2454.42,4512.12 r90 bottom value=33.2
R231 "RC0201JR-0710RL" 0201L 3050,3181.79 r90 bottom value=10
R232 "RC0201JR-0710RL" 0201L 2686,3181.79 r90 bottom value=10
R233 "ERJ-2GE0R00X" 0402L 2912,3181.79 r270 bottom value=0
R234 "ERJ-1GNF33R2C" FP-ERJ-1GNF33R2C_0201-MFG 1456.34,2590.02 r0 top value=33.2
R235 "RC0201JR-0710RL" 0201L 2947.88,3181.79 r90 bottom value=10
R236 "RC0201JR-0710RL" 0201L 2551,3171.79 r90 bottom value=10
R237 "ERJ-1GNF33R2C" FP-ERJ-1GNF33R2C_0201-MFG 1456.65,2632.81 r0 top value=33.2
R238 "ERJ-1GNF33R2C" FP-ERJ-1GNF33R2C_0201-MFG 1455.93,2676.12 r0 top value=33.2
R239 "ERJ-1GNF33R2C" FP-ERJ-1GNF33R2C_0201-MFG 1457.37,2718.89 r0 top value=33.2
R240 "ERJ-1GNF33R2C" FP-ERJ-1GNF33R2C_0201-MFG 1457.63,2761.09 r0 top value=33.2
R242 "ERJ-2GEJ101X" 0402L 1162.88,3142.47 r180 bottom value=100
R243 "CRCW02014K70FKED" 0201_033L 740.29,1405.09 r0 bottom value=4.70k
R244 "ERJ-1GNJ220C" 0201L 292.66,1427.81 r0 bottom value=22
R245 "ERJ-1GNF33R2C" FP-ERJ-1GNF33R2C_0201-MFG 1551.02,2839.29 r0 top value=33.2
R246 "ERJ-2GE0R00X" 0402L 1162.88,3105.99 r0 bottom value=0
R247 "ERJ-1GNF33R2C" FP-ERJ-1GNF33R2C_0201-MFG 1297.46,2984.53 r90 bottom value=33.2
R248 "CRCW06031M00FKEA" 0603L 1008.66,3149.13 r270 bottom value=1.00Meg
R249 "ERJ-1GNF33R2C" FP-ERJ-1GNF33R2C_0201-MFG 1162.76,3050.42 r0 top value=33.2
R250 "CRCW040210K0FKED" 0402L 551.66,3247.26 r180 top value=10.0k
R251 "CRCW040210K0FKED" 0402L 1166.09,3293.72 r0 bottom value=10.0k
R252 "CRCW04022K49FKED" 0402L 1401.29,3360.05 r90 top value=2.49k
R253 "CRCW04022K49FKED" 0402L 1407.02,3360.97 r90 bottom value=2.49k
R254 "CRCW04022K49FKED" 0402L 1474.75,3360.05 r90 top value=2.49k
R255 "CRCW04022K49FKED" 0402L 1630.02,3056.06 r0 top value=2.49k
R256 "CRCW04022K49FKED" 0402L 1630.02,3103.94 r0 top value=2.49k
R257 "CRCW04022K49FKED" 0402L 1630.02,3151.97 r0 top value=2.49k
R258 "CRCW04022K49FKED" 0402L 1630.02,3200.99 r0 top value=2.49k
R259 "ERJ-2GE0R00X" 0402L 1010.04,3259.5 r270 bottom value=0
R260 "CRCW040226R7FKED" 0402L 1377.98,3618.51 r0 bottom value=26.7
R261 "ERJ-2GEJ511X" 0402L 1420,4222.31 r0 top value=510
R262 "ERJ-2GEJ511X" 0402L 1100.93,1399.56 r90 top value=510
R263 "ERJ-2GEJ511X" 0402L 242.79,1822.86 r180 top value=510
R264 "CRCW040210K0FKED" 0402L 164.14,1316.33 r0 top value=10.0k
R265 "CRCW04020000Z0EDHP" 0402L 1416.18,3586.4 r180 bottom value=0
R266 "ERJ-2GEJ511X" 0402L 49.46,1736.94 r90 top value=510
R267 "CRCW040210R0JNED" 0402L 185.16,1385.97 r270 top value=10
R268 "CRCW040210R2FKED" 0402L 88.6,1227 r180 top value=10.2
R269 "ERJ-2GE0R00X" 0402L 2083.18,3718.43 r180 bottom value=0
R270 "CRCW04020000Z0EDHP" 0402L 1416.18,3554.12 r180 bottom value=0
R271 "CRCW040210K0FKED" 0402L 2314.95,3255.02 r270 bottom value=10.0k
R272 "CRCW040210K0FKED" 0402L 2386,3254.36 r270 bottom value=10.0k
R273 "CRCW040210K0FKED" 0402L 2623.66,4341.41 r90 bottom value=10.0k
R274 "CRCW040226R7FKED" 0402L 1377.98,3522.02 r180 bottom value=26.7
R275 "ERJ-P06F1001V" 0805L 634.18,3525.09 r0 top value=1.00k
R276 "CRCW04022K94FKED" 0402L 162.12,732.43 r180 top value=2.94k
R277 "CRCW04022K94FKED" 0402L 162.12,691.43 r180 top value=2.94k
R278 "CRCW0402100KFKED" 0402L 2788.54,3561.4 r270 bottom value=100k
R279 "CRCW0402100KFKED" 0402L 2752.31,3561.4 r270 bottom value=100k
R280 "CRCW04022K20JNED" 0402L 1171.49,2172.7 r270 bottom value=2.2k
R281 "ERJ-P06F1001V" 0805L 634.18,3615.44 r0 top value=1.00k
R282 "CRCW0805100KJNEA" 0805_HV 489.23,3615.44 r0 top value=100k
R283 "CRCW040210K0FKED" 0402L 1737.74,1206.86 r180 top value=10.0k
R284 "CRCW0402330KFKED" 0402L 2828,1002.31 r270 bottom value=330k
R285 "CRCW0402330KFKED" 0402L 2755.58,1002.31 r90 bottom value=330k
R286 "CRCW04022K49FKED" 0402L 1429.15,2726.94 r90 bottom value=2.49k
R287 "CRCW04022K49FKED" 0402L 1520.83,2582.54 r90 bottom value=2.49k
R288 "CRCW04022K49FKED" 0402L 1583.69,2582.59 r90 bottom value=2.49k
R289 "CRCW04022K49FKED" 0402L 1508.33,2858.98 r270 top value=2.49k
R290 "ERJ-1GNF33R2C" FP-ERJ-1GNF33R2C_0201-MFG 1432.72,2590.02 r180 top value=33.2
R291 "ERJ-2GE0R00X" 0402L 1210.57,1213.5 r270 bottom value=0
R292 "ERJ-2GEJ511X" 0402L 1699.06,1501.05 r180 bottom value=510
R293 "CRCW060348K7FKEA" 0603L 870.42,2904.77 r270 top value=48.7k
R294 "CRCW060345K3FKEA" 0603L 927.83,2904.77 r90 top value=45.3k
R295 "ERJ-2GE0R00X" 0402L 918.99,3019.03 r90 top value=0
R296 "CRCW040210K0FKED" 0402L 2497.52,1293.73 r270 top value=10.0k
R297 "ERJ-2GE0R00X" 0402L 1451.34,246.66 r180 top value=0
R298 "CRCW0402750RFKED" 0402L 1451.34,98.61 r0 top value=750
R299 "CRCW040210K0FKED" 0402L 1451.34,210.44 r180 top value=10.0k
R300 "CRCW04027K87FKED" 0402L 1451.34,135.11 r0 top value=7.87k
R301 "CRCW040210K0FKED" 0402L 2531.76,3302.56 r90 bottom value=10.0k
R302 "CRCW040282K5FKED" 0402L 1451.34,171.07 r180 top value=82.5k
R303 "CRCW040210K0FKED" 0402L 2489.92,3302.56 r270 bottom value=10.0k
R304 "CRCW0402750RFKED" 0402L 1682.58,90.41 r0 top value=750
R305 "CRCW040210K0FKED" 0402L 1682.58,199.99 r180 top value=10.0k
R306 "CRCW04027K87FKED" 0402L 1682.58,128.35 r0 top value=7.87k
R307 "CRCW040282K5FKED" 0402L 1682.58,165.74 r180 top value=82.5k
R308 "CRCW0402750RFKED" 0402L 1907.03,96.1 r0 top value=750
R309 "CRCW040210K0FKED" 0402L 2607.16,3450.13 r270 bottom value=10.0k
R310 "CRCW040210K0FKED" 0402L 1907.03,204.71 r180 top value=10.0k
R311 "CRCW04027K87FKED" 0402L 1907.03,133.08 r0 top value=7.87k
R312 "CRCW040210K0FKED" 0402L 2572.88,3450.13 r90 bottom value=10.0k
R313 "CRCW040282K5FKED" 0402L 1907.03,169.19 r180 top value=82.5k
R314 "CRCW040210K0FKED" 0402L 551.66,3213.22 r0 top value=10.0k
R315 "CRCW04021K00FKED" 0402L 905.35,1112.53 r270 top value=1.00k
R316 "ERJ-2GE0R00X" 0402L 1830.67,3979.4 r180 bottom value=0
R317 "CRCW02010000Z0ED" 0201L 1821.32,1399.06 r0 bottom value=0
R318 "CRCW02010000Z0ED" 0201L 2016.7,1463.53 r180 bottom value=0
R319 "CRCW02010000Z0ED" 0201L 1821.76,1485.22 r180 bottom value=0
R320 "CRCW02010000Z0ED" 0201L 749.22,1174.67 r180 top value=0
R321 "CRCW02010000Z0ED" 0201L 244.45,1514.71 r0 bottom value=0
R322 "CRCW02010000Z0ED" 0201L 818.44,922.93 r0 bottom value=0
R323 "CRCW02010000Z0ED" 0201L 818.52,895.01 r0 bottom value=0
R324 "CRCW02010000Z0ED" 0201L 2760,4341.41 r90 bottom value=0
R325 "ERJ-1GNF33R2C" FP-ERJ-1GNF33R2C_0201-MFG 1433.03,2632.81 r180 top value=33.2
R326 "CRCW040210K0FKED" 0402L 2668.4,4431.89 r270 bottom value=10.0k
R327 "CRCW02010000Z0ED" 0201L 818.44,922.93 r0 top value=0
R328 "CRCW02010000Z0ED" 0201L 262.36,838.88 r0 top value=0
R329 "CRCW02010000Z0ED" 0201L 262.36,800.66 r0 top value=0
R330 "ERJ-2GE0R00X" 0402L 1480.13,4152.19 r0 bottom value=0
R331 "CRCW04021K00FKED" 0402L 2147.34,362.23 r90 top value=1.00k
R332 "CRCW04021K00FKED" 0402L 1082.76,825.81 r270 top value=1.00k
R333 "ERJ-2GEJ101X" 0402L 78.84,1807.13 r0 top value=100
R334 "CRCW02010000Z0ED" 0201L 215.95,1867.45 r90 top value=0
R335 "CRCW040210K0FKED" 0402L 179.39,1871.75 r270 top value=10.0k
R336 "ERJ-1GNF33R2C" FP-ERJ-1GNF33R2C_0201-MFG 1432.3,2676.12 r180 top value=33.2
R337 "CRCW040211K0FKED" 0402L 925.03,2418.89 r180 top value=11.0k
R338 "ERJ-1GNF33R2C" FP-ERJ-1GNF33R2C_0201-MFG 1433.75,2718.89 r180 top value=33.2
R339 "ERJ-1GNF33R2C" FP-ERJ-1GNF33R2C_0201-MFG 1434.01,2761.09 r180 top value=33.2
R340 "CRCW04022K20JNED" 0402L 1087.72,2955.53 r90 top value=2.2k
R341 "CRCW02010000Z0ED" 0201L 818.52,895.01 r0 top value=0
R342 "CRCW04022K20JNED" 0402L 1143.2,2955.53 r90 top value=2.2k
R344 "CRCW02010000Z0ED" 0201L 1083.65,2323.17 r90 top value=0
R345 "CRCW02010000Z0ED" 0201L 808.52,804.9 r0 bottom value=0
R346 "CSNL1206FT1L00" 1206L 2931.22,1786.04 r180 top value=0.001
R347 "ERJ-2GEJ511X" 0402L 3062.49,1972.79 r270 top value=510
R348 "CRCW040210R2FKED" 0402L 2905.36,1890.36 r90 top value=10.2
R349 "CRCW02010000Z0ED" 0201L 808.52,776.9 r0 bottom value=0
R350 "CRCW040210K0FKED" 0402L 1162.88,3222.97 r180 top value=10.0k
R351 "CRCW02010000Z0ED" 0201L 818.52,807.34 r0 top value=0
R352 "CRCW040210R2FKED" 0402L 2954.95,1890.49 r90 top value=10.2
R353 "ERJ-2GE0R00X" 0402L 2540.51,1481.93 r180 top value=0
R354 "ERJ-2GE0R00X" 0402L 2444.88,1557.99 r270 top value=0
R355 "ERJ-2GE0R00X" 0402L 2403.67,1557.99 r270 top value=0
R356 "ERJ-2GE0R00X" 0402L 2362.88,1557.99 r270 top value=0
R357 "ERJ-2GE0R00X" 0402L 2358.88,1290.94 r90 top value=0
R358 "ERJ-2GE0R00X" 0402L 2317.88,1290.94 r90 top value=0
R359 "ERJ-2GE0R00X" 0402L 2440.88,1290.94 r90 top value=0
R360 "ERJ-2GE0R00X" 0402L 2399.67,1290.94 r90 top value=0
R361 "CRCW02010000Z0ED" 0201L 818.52,779.34 r0 top value=0
R362 "CRCW040210R2FKED" 0402L 1586.86,4152.19 r0 bottom value=10.2
R363 "CRCW02010000Z0ED" 0201L 728.44,745.76 r0 top value=0
R364 "CRCW02010000Z0ED" 0201L 728.44,717.76 r0 top value=0
R365 "CRCW02010000Z0ED" 0201L 728.44,686.7 r0 top value=0
R366 "CRCW02010000Z0ED" 0201L 728.44,658.7 r0 top value=0
R367 "ERJ-2GE0R00X" 0402L 800.05,3257.81 r270 bottom value=0
R369 "ERJ-1GNF33R2C" FP-ERJ-1GNF33R2C_0201-MFG 1132.04,2320.17 r90 top value=33.2
R370 "CRCW02010000Z0ED" 0201L 1046.92,2323.17 r90 top value=0
R371 "CRCW02010000Z0ED" 0201L 2418.82,3263.02 r270 bottom value=0
R374 "ERJ-1GNF33R2C" FP-ERJ-1GNF33R2C_0201-MFG 739.11,1359.56 r180 bottom value=33.2
R375 "ERJ-1GNF33R2C" FP-ERJ-1GNF33R2C_0201-MFG 292.66,1346.03 r180 bottom value=33.2
R376 "ERJ-1GNF33R2C" FP-ERJ-1GNF33R2C_0201-MFG 292.66,1388.1 r180 bottom value=33.2
R377 "ERJ-1GNF33R2C" FP-ERJ-1GNF33R2C_0201-MFG 1906.18,1063.53 r90 top value=33.2
R379 "CRCW02010000Z0ED" 0201L 2351,3263.02 r270 bottom value=0
R380 "CRCW040233R2FKED" 0402L 2583.89,4341.41 r270 bottom value=33.2
R381 "CRCW040233R2FKED" 0402L 2063.32,4190.81 r0 bottom value=33.2
R386 "CRCW040233R2FKED" 0402L 2719,3181.79 r90 bottom value=33.2
R387 "CRCW040233R2FKED" 0402L 2096.4,1194.56 r0 bottom value=33.2
R388 "CRCW040233R2FKED" 0402L 2096.97,1246.13 r0 bottom value=33.2
R389 "CRCW040233R2FKED" 0402L 2097.56,1296.89 r0 bottom value=33.2
R390 "CRCW02010000Z0ED" 0201L 263.62,732.43 r0 top value=0
R391 "CRCW02010000Z0ED" 0201L 262.34,690.95 r0 top value=0
R392 "CRCW040233R2FKED" 0402L 3035.26,4072.81 r180 bottom value=33.2
R399 "CRCW02010000Z0ED" 0201L 1817.43,1063.53 r270 top value=0
R400 "ERJ-2GE0R00X" 0402L 790.52,2327.93 r0 bottom value=0
R401 "ERJ-2GE0R00X" 0402L 360.63,2122.19 r180 bottom value=0
R409 "CRCW040210K0FKED" 0402L 361.36,4718.01 r90 top value=10.0k
R413 "ERJ-1GNF33R2C" FP-ERJ-1GNF33R2C_0201-MFG 1171.49,2320.17 r90 top value=33.2
R414 "CRCW06031M00FKEAC" FP-CRCW06031M00FKEAC_0603-MFG 1065.09,2249.26 r180 top value=1M
R416 "CRCW040210K0FKED" 0402L 1032.2,4620.96 r180 top value=10.0k
R417 "CRCW040210K0FKED" 0402L 1032.2,4672.69 r0 top value=10.0k
R418 "CRCW040210K0FKED" 0402L 268.01,1119.56 r180 top value=10.0k
R419 "ERJ-2GE0R00X" 0402L 403.86,3009.18 r90 bottom value=0
R422 "CRCW02010000Z0ED" 0201L 265.9,1082.03 r0 top value=0
R423 "CRCW02010000Z0ED" 0201L 265.9,1050.53 r0 top value=0
R424 "CRCW02010000Z0ED" 0201L 747.25,1056 r0 top value=0
R425 "CRCW02010000Z0ED" 0201L 747.25,1017.19 r0 top value=0
R503 "CRCW0201100RFKED" 0201L 291.89,1297.35 r0 bottom value=100
R508 "CRCW02014K70FKED" 0201_033L 244.45,1467.61 r0 bottom value=4.70k
R512 "CRCW02014K70FKED" 0201_033L 740.29,1441.92 r0 bottom value=4.70k
S1 "CJS-1201TA" SW_CJS_1201A 2676.28,1432.34 r90 top
S2 "CJS-1201TA" SW_CJS_1201A 1852.05,1156.66 r270 bottom
SW1 "KMR243GLFG" SW_KMR243GLFG 96.47,1547 r270 top
SW2 "KMR243GLFG" SW_KMR243GLFG 90.65,1932.78 r270 top
SW3 "KMR243GLFG" SW_KMR243GLFG 88.65,535.07 r270 top
TP1 "TESTPOINT" TP_25MIL-SMT 1351,4066.81 r0 top
TP2 "TESTPOINT" TP_25MIL-SMT 1353,3254.81 r0 top
TP3 "TESTPOINT" TP_25MIL-SMT 1066.56,3321.29 r90 top
TP4 "TESTPOINT" TP_25MIL-SMT 221.49,1616.56 r180 top
TP5 "TESTPOINT" TP_25MIL-SMT 1267.43,2214.09 r90 top
TP6 "TESTPOINT" TP_25MIL-SMT 786.03,2267.32 r90 top
TP7 "5001" Keystone5001 717.82,4637.51 r90 bottom locked
TP8 "TESTPOINT" TP_25MIL-SMT 1174.27,1478.02 r270 bottom
TP9 "5001" Keystone5001 3213.15,1863.49 r90 top locked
